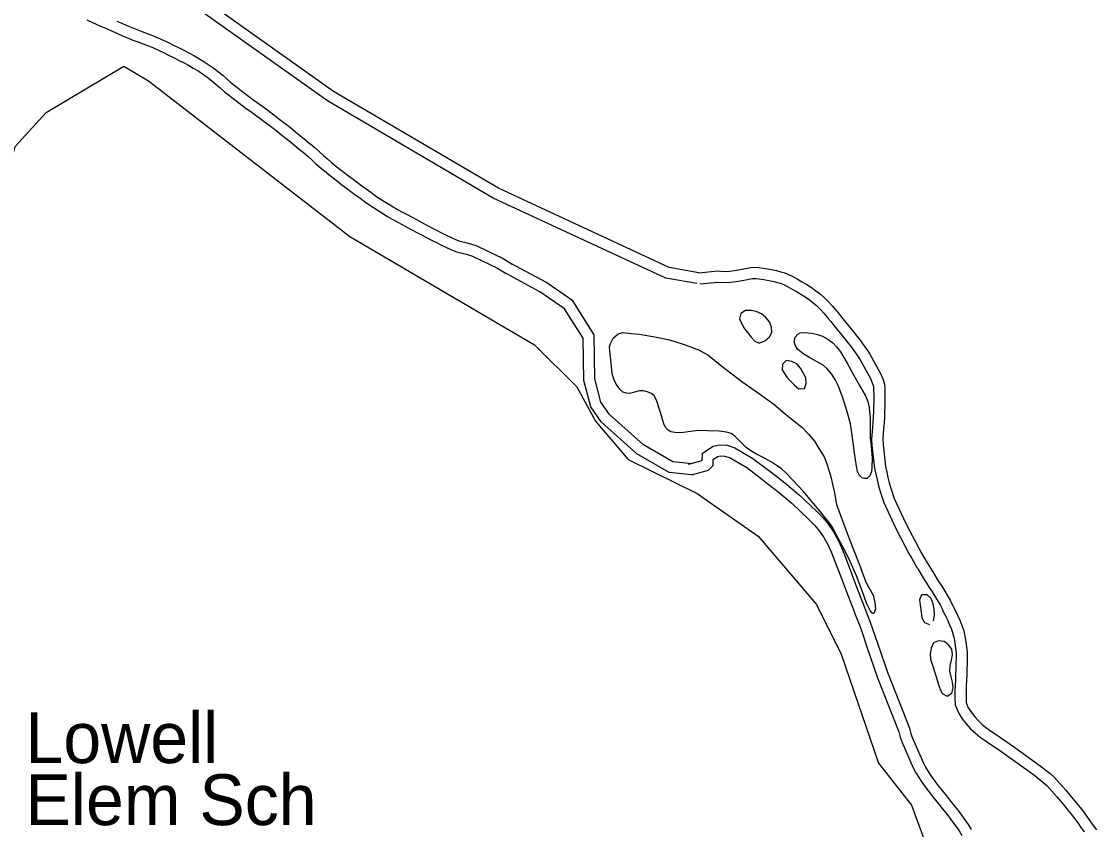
# Model space of a CAD drawing. Extents: x 1364363 to 1407445, y 538563 to 573342.
# Drawn here: x 1376165 to 1379335, y 562586 to 564968 of the extents above; entities that cross this region are included whole.
import ezdxf

# ---------------------------------------------------------------- set-up
doc = ezdxf.new("R2010")
doc.units = 0
for name, color, linetype in [('Exist Boundary Political City Limit New', 7, 'Continuous'), ('Exist Cultural Educational Facility High Label', 7, 'Continuous'), ('Exist Hydrographic Buffer Line', 7, 'Continuous'), ('Exist Hydrographic Creek Double Shore', 7, 'Continuous'), ('Exist Hydrographic Island Shore', 7, 'Continuous')]:
    doc.layers.add(name, color=color, linetype=linetype)

msp = doc.modelspace()

# ---------------------------------------------------------------- linework, layer by layer
at = {"layer": 'Exist Boundary Political City Limit New'}
for points in [[(1375206.1, 561788.9), (1375573.2, 562500.8), (1375743.9, 562885.2), (1375884.1, 563257.4), (1375926.8, 563806.6), (1376146.1, 564599.8), (1376237.6, 564700.5), (1376466.9, 564836.6)], [(1376466.9, 564836.6), (1376539.4, 564793.1), (1377132.8, 564334.4), (1377677.9, 564014.8), (1377802.1, 563890.9), (1377857.2, 563790.4), (1377953.9, 563676.6), (1378157.5, 563576.2), (1378336.9, 563450.7), (1378509.4, 563249.8), (1378581.9, 563102.5), (1378692.2, 562781.1), (1378788.9, 562657.2), (1378864.8, 562451.4)]]:
    msp.add_lwpolyline(points, dxfattribs=at)
at = {"layer": 'Exist Hydrographic Buffer Line'}
for points in [[(1378155.9, 564195.4), (1378064.8, 564211.6), (1377555.5, 564447.5), (1377066.8, 564734.5), (1376428.4, 565188.7)], [(1376445.6, 564969.7), (1376460.5, 564963.1), (1376475.4, 564956.6), (1376490.1, 564950.2), (1376504.5, 564944.4), (1376519.3, 564938.9), (1376534.8, 564933.3), (1376550.9, 564927.2), (1376567.1, 564920.5), (1376582.7, 564913.3), (1376597.8, 564906), (1376612.8, 564898.9), (1376627.9, 564891.5), (1376642.9, 564883.9), (1376658, 564876), (1376673, 564867.9), (1376687.8, 564859.4), (1376702.7, 564850.4), (1376717.3, 564840.8), (1376731.8, 564830.6), (1376745.6, 564819.9), (1376759, 564808.8), (1376771.9, 564797.6), (1376783.4, 564787.3), (1376846.8, 564738.7), (1376859.8, 564729.6), (1376873.5, 564719.8), (1376887, 564709.8), (1376900.4, 564699.8), (1376913.6, 564689.7), (1376926.7, 564679.6), (1376939.7, 564669.4), (1376952.7, 564659.3), (1376965.7, 564649), (1376978.7, 564638.6), (1377004.5, 564617.7), (1377017.2, 564607)], [(1377017.8, 564606.6), (1377030.4, 564595.6), (1377054.9, 564573.6), (1377066.8, 564563), (1377078.7, 564552.8), (1377090.9, 564543), (1377103.6, 564533.1), (1377116.5, 564523.2), (1377129.4, 564513.3), (1377142.3, 564503.5), (1377155.3, 564493.8), (1377168.4, 564484.1), (1377181.5, 564474.5), (1377194.6, 564465.1), (1377207.8, 564455.7), (1377220.4, 564446.9), (1377260.4, 564421.9), (1377273.8, 564414.4), (1377288.1, 564406.6), (1377302.4, 564398.8), (1377331.1, 564383.3), (1377345.6, 564375.7), (1377360, 564368), (1377374.4, 564360.4), (1377388.9, 564352.9), (1377403.4, 564345.4), (1377417.4, 564338.3), (1377444.9, 564325.4), (1377457.1, 564321.1), (1377471.5, 564317.6), (1377489.1, 564313.2), (1377507.7, 564306.6), (1377584.6, 564269.5), (1377611.5, 564253)], [(1378143.7, 563664.2), (1378084.9, 563670.3), (1377999.1, 563720.4), (1377898.5, 563809.6), (1377873.5, 563846.2), (1377855.5, 563914.3), (1377853.2, 564044.6), (1377790.1, 564144.5), (1377710.4, 564199.4), (1377610, 564253.8)], [(1378164.6, 564195), (1378218.4, 564199.9), (1378234.6, 564198.4), (1378254.3, 564199.6), (1378272.5, 564201.6), (1378290.1, 564204.7), (1378306, 564207.9), (1378319.8, 564210.2), (1378331, 564210.7), (1378354.1, 564207.4)], [(1378353.3, 564207.6), (1378368.9, 564205), (1378383.6, 564201.9), (1378397.7, 564198.2), (1378405, 564195.8)], [(1378405.1, 564195.8), (1378410, 564194.2), (1378421.8, 564188.2), (1378435.6, 564180.6), (1378449.6, 564172.7), (1378463, 564164.8), (1378475.8, 564156.5), (1378487.9, 564148), (1378499.2, 564139.1), (1378509.9, 564129.5), (1378520.5, 564119), (1378530.8, 564107.9), (1378540.9, 564096.3), (1378543.5, 564093.1)], [(1378543.7, 564092.9), (1378551.2, 564084), (1378561.3, 564071.4), (1378592.3, 564032.9), (1378602.5, 564020.2), (1378612.2, 564007.9), (1378621.5, 563995.3), (1378630.4, 563982.7), (1378638.2, 563970.6), (1378668, 563915.5), (1378673.5, 563903.2), (1378676.7, 563893.2), (1378677.4, 563881.7), (1378677.7, 563866.3), (1378677.7, 563850.5), (1378677.4, 563834.4), (1378677.1, 563818.3), (1378676.5, 563802.5), (1378675.6, 563786.9), (1378674.2, 563770.9), (1378671.5, 563737.3), (1378672.6, 563718.1), (1378680.4, 563651.1), (1378683.8, 563633.4), (1378687.5, 563616.6), (1378691.7, 563599.3), (1378696.9, 563582.3), (1378707.9, 563549.8), (1378743.1, 563473.5), (1378781.6, 563399.6), (1378790, 563384.7), (1378807.3, 563355.2)], [(1378131.7, 563663.2), (1378171.7, 563674.1), (1378172.5, 563695.1), (1378204.2, 563716.6), (1378224.2, 563720.5), (1378245.4, 563719.1), (1378267.9, 563711.7), (1378321.3, 563680.2), (1378367.2, 563645.7), (1378386.8, 563630.5), (1378415.9, 563607.9), (1378459.3, 563572), (1378509, 563524.2), (1378528.2, 563504.7), (1378544.4, 563485.3), (1378558.9, 563464), (1378573, 563438.9), (1378582.7, 563417.7), (1378593.3, 563390.8), (1378612, 563340.3), (1378627.3, 563301.3), (1378650.4, 563240.5), (1378653.7, 563232.3)], [(1378807.6, 563354.8), (1378823.8, 563328.2), (1378841.5, 563299.6), (1378850.5, 563286.3), (1378874.2, 563246), (1378880.2, 563234.5)], [(1378653.7, 563232.2), (1378667.4, 563197.4), (1378674.3, 563177.2)], [(1378880, 563234.8), (1378888.4, 563218), (1378895.3, 563203.8), (1378901.7, 563189.7), (1378907.3, 563176.2), (1378911.5, 563163.3), (1378914.7, 563149.7), (1378917.1, 563135), (1378920.8, 563105.9), (1378920.7, 563092.1), (1378920.3, 563076.1), (1378919.8, 563059.9), (1378919.2, 563043.6), (1378918.5, 563027.1), (1378918, 563010.5), (1378917.4, 562993.8), (1378917.2, 562976.2), (1378918.1, 562953.4), (1378927.4, 562929.9), (1378938.9, 562912.3), (1378950.3, 562897.3), (1378963.2, 562882.7), (1378977.6, 562869.8), (1378991.9, 562858.6), (1379006.3, 562848.2), (1379020.2, 562838.9), (1379045.5, 562821.6)], [(1378674.3, 563177.3), (1378688.7, 563135.6), (1378720.4, 563043.6)], [(1378720, 563044.9), (1378782.8, 562884.6), (1378787.5, 562868.1), (1378792.1, 562854.8), (1378824.1, 562782), (1378830.7, 562769.3), (1378838.3, 562756.7), (1378846.6, 562744.2), (1378855.7, 562731.7), (1378865.2, 562719), (1378874.9, 562706.4), (1378895.2, 562681.1), (1378905.6, 562668.3), (1378916, 562655.2), (1378926.4, 562642.1), (1378936.7, 562628.5), (1378946.8, 562614.6), (1378956.7, 562600.3), (1378965.6, 562586.4)], [(1379045.4, 562821.6), (1379073.7, 562802.1), (1379152.5, 562744.9), (1379164.6, 562735.4), (1379176.6, 562725.6), (1379187.9, 562715.7), (1379219.2, 562680.8)], [(1379219.2, 562680.8), (1379240.1, 562655.5), (1379250.4, 562643.1), (1379260.3, 562630.7), (1379270, 562618.2), (1379279.4, 562605.4), (1379288.9, 562592.2), (1379298.4, 562578.9)]]:
    msp.add_lwpolyline(points, dxfattribs=at)
at = {"layer": 'Exist Hydrographic Creek Double Shore'}
for points in [[(1378161.6, 564227.7), (1378074.8, 564243.2), (1377570.8, 564476.6), (1377084.7, 564762), (1376443.7, 565218.1)], [(1376357.4, 564973.4), (1376372.3, 564966.6), (1376387.3, 564959.9), (1376402.3, 564953.1), (1376417.2, 564946.4), (1376432.3, 564939.7), (1376447.3, 564933.1), (1376462.3, 564926.5), (1376477.4, 564920), (1376492.6, 564913.8), (1376508, 564908.1), (1376523.5, 564902.5), (1376538.8, 564896.7), (1376553.9, 564890.4), (1376568.8, 564883.6), (1376583.6, 564876.5), (1376598.5, 564869.3), (1376613.3, 564862.1), (1376627.9, 564854.7), (1376642.6, 564847.1), (1376656.9, 564839.2), (1376671.2, 564831.1), (1376685.2, 564822.6), (1376698.9, 564813.7), (1376712.2, 564804.2), (1376725.1, 564794.2), (1376737.8, 564783.7), (1376750.2, 564773), (1376762.5, 564762), (1376827.4, 564712.2), (1376840.9, 564702.8), (1376854.2, 564693.2), (1376867.4, 564683.5), (1376880.6, 564673.7), (1376893.6, 564663.7), (1376906.6, 564653.7), (1376919.5, 564643.6), (1376932.4, 564633.5), (1376945.3, 564623.3), (1376958.2, 564613.1), (1376970.9, 564602.7), (1376983.6, 564592.4), (1376996.2, 564581.8)], [(1376996.2, 564581.8), (1377008.6, 564571), (1377020.8, 564560.1), (1377033, 564549.1), (1377045.3, 564538.2), (1377057.8, 564527.6), (1377070.5, 564517.3), (1377083.4, 564507.2), (1377096.5, 564497.2), (1377109.5, 564487.2), (1377122.6, 564477.3), (1377135.7, 564467.4), (1377149, 564457.7), (1377162.2, 564448), (1377175.5, 564438.4), (1377188.8, 564428.9), (1377202.3, 564419.5), (1377243.7, 564393.7), (1377257.9, 564385.7), (1377272.4, 564377.8), (1377286.8, 564370), (1377301.2, 564362.2), (1377315.7, 564354.4), (1377330.2, 564346.7), (1377344.7, 564339), (1377359.2, 564331.4), (1377373.8, 564323.8), (1377388.4, 564316.3), (1377403, 564308.8), (1377432.3, 564295.1), (1377447.6, 564289.6), (1377463.7, 564285.7), (1377479.7, 564281.8), (1377495.1, 564276.3), (1377568.8, 564240.7), (1377594.3, 564225)], [(1378161.6, 564227.7), (1378218.4, 564232.8), (1378235.1, 564231.3), (1378251.5, 564232.3), (1378267.8, 564234.1), (1378284, 564236.9), (1378300.1, 564240.2), (1378316.3, 564242.8), (1378332.5, 564243.7), (1378358.8, 564239.9)], [(1378358.8, 564239.9), (1378375, 564237.2), (1378391.1, 564233.9), (1378407.1, 564229.7), (1378415.4, 564227)], [(1378140.4, 563631.6), (1378074.4, 563638.4), (1377979.7, 563693.7), (1377873.7, 563787.7), (1377843.3, 563832.4), (1377822.8, 563909.8), (1377820.5, 564034.9), (1377766, 564121.3), (1377693.2, 564171.4), (1377594.3, 564225)], [(1378415.4, 564227), (1378422.6, 564224.5), (1378437.2, 564217.2), (1378451.6, 564209.2), (1378466, 564201.1), (1378480.3, 564192.7), (1378494.1, 564183.7), (1378507.5, 564174.3), (1378520.4, 564164.2), (1378532.5, 564153.3), (1378544, 564141.9), (1378555.2, 564129.9), (1378566, 564117.5), (1378568.8, 564114)], [(1378568.8, 564114), (1378576.5, 564104.8), (1378586.9, 564091.9), (1378617.9, 564053.5), (1378628.2, 564040.7), (1378638.4, 564027.7), (1378648.1, 564014.5), (1378657.5, 564001.1), (1378666.5, 563987.3), (1378697.4, 563930), (1378704.2, 563915), (1378709.2, 563899.4), (1378710.2, 563883), (1378710.5, 563866.6), (1378710.5, 563850.2), (1378710.2, 563833.8), (1378709.9, 563817.4), (1378709.3, 563800.9), (1378708.3, 563784.4), (1378706.8, 563768.2), (1378704.4, 563737), (1378705.3, 563720.9), (1378712.8, 563656.2), (1378716, 563640), (1378719.5, 563624), (1378723.4, 563608), (1378728.2, 563592.4), (1378738.4, 563562), (1378772.6, 563488), (1378810.5, 563415.3), (1378818.5, 563401), (1378835.6, 563371.8)], [(1378140.4, 563631.6), (1378190.4, 563645.2), (1378204, 563658.9), (1378204.7, 563677.3), (1378217.1, 563685.7), (1378226.3, 563687.5), (1378239.1, 563686.6), (1378254.3, 563681.7), (1378303.1, 563652.9), (1378347.3, 563619.7), (1378366.7, 563604.6), (1378395.4, 563582.3), (1378437.4, 563547.5), (1378485.9, 563500.9), (1378503.8, 563482.6), (1378518.2, 563465.4), (1378531, 563446.7), (1378543.7, 563424), (1378552.5, 563404.8), (1378562.6, 563379.1), (1378581.4, 563328.6), (1378596.7, 563289.5), (1378619.8, 563228.7), (1378623.2, 563220.1)], [(1378835.6, 563371.8), (1378851.7, 563345.3), (1378869, 563317.4), (1378878.3, 563303.9), (1378903, 563261.9), (1378909.3, 563249.5)], [(1378909.3, 563249.5), (1378917.8, 563232.6), (1378925, 563217.7), (1378931.8, 563202.7), (1378938, 563187.6), (1378943.2, 563172.1), (1378946.9, 563156), (1378949.5, 563139.8), (1378953.6, 563107.9), (1378953.5, 563091.6), (1378953.1, 563075.2), (1378952.6, 563058.8), (1378952, 563042.3), (1378951.3, 563025.9), (1378950.8, 563009.5), (1378950.2, 562993.1), (1378950, 562976.6), (1378950.7, 562960.2), (1378956.7, 562945.1), (1378965.7, 562931.2), (1378975.7, 562918.2), (1378986.5, 562905.9), (1378998.7, 562894.9), (1379011.7, 562884.8), (1379025, 562875.1), (1379038.6, 562866.1), (1379064, 562848.6)], [(1378623.2, 563220.1), (1378636.6, 563186.1), (1378643.3, 563166.6)], [(1378643.3, 563166.6), (1378657.7, 563124.9), (1378689.4, 563032.9)], [(1378689.4, 563032.9), (1378751.7, 562874.1), (1378756.2, 562858.2), (1378761.5, 562842.8), (1378794.5, 562767.8), (1378802.1, 562753.3), (1378810.5, 562739.2), (1378819.6, 562725.5), (1378829.3, 562712.2), (1378839.1, 562699.1), (1378849.2, 562686.1), (1378859.4, 562673.3), (1378869.7, 562660.5), (1378880, 562647.7), (1378890.3, 562634.9), (1378900.4, 562622), (1378910.4, 562608.9), (1378920, 562595.7), (1378929.3, 562582.1), (1378937.9, 562568.7)], [(1379064, 562848.6), (1379092.7, 562828.9), (1379172.2, 562771.1), (1379185.1, 562761), (1379197.8, 562750.6), (1379210.1, 562739.8), (1379244.5, 562701.7)], [(1379244.5, 562701.7), (1379265.4, 562676.4), (1379275.9, 562663.8), (1379286.1, 562651), (1379296.2, 562638), (1379305.9, 562624.7), (1379315.5, 562611.4), (1379325.1, 562598.1), (1379334.7, 562584.7)]]:
    msp.add_lwpolyline(points, dxfattribs=at)
at = {"layer": 'Exist Hydrographic Island Shore'}
for points in [[(1378330.7, 564113.4), (1378316.2, 564116.7), (1378299.8, 564116.4), (1378285.8, 564107.6), (1378282, 564091.5), (1378295.2, 564065), (1378315.9, 564037.6), (1378326.9, 564025.8), (1378340.1, 564020.4), (1378356.9, 564026.5), (1378370.8, 564038.5)], [(1378370.8, 564038.5), (1378377.7, 564051.4), (1378376, 564067.5), (1378370.6, 564083.1), (1378360, 564095.7), (1378347.2, 564106.1), (1378330.7, 564113.4)], [(1378660.2, 563245.7), (1378656.6, 563253.4), (1378643.8, 563289.9), (1378626.5, 563333.5), (1378608.5, 563376), (1378592.1, 563408.5), (1378567.7, 563454.1), (1378555.2, 563478.7), (1378546.6, 563491.4), (1378516.1, 563528.9), (1378470, 563583.9), (1378441.1, 563613.7), (1378417.9, 563638.6), (1378406.3, 563648.9), (1378393.5, 563658.7), (1378378.4, 563668.5), (1378357.8, 563679.7), (1378329.8, 563693.5), (1378315.1, 563702.7), (1378301.2, 563712.5), (1378298.4, 563715.3), (1378285.5, 563728.3), (1378268.1, 563745.9), (1378257.1, 563753.3), (1378244.1, 563757.8), (1378221.7, 563760.7), (1378187.3, 563761.5), (1378161.8, 563762.2), (1378137.5, 563759.8), (1378110.1, 563755.7), (1378091.2, 563756.2), (1378079.9, 563758.3), (1378071.2, 563763.8), (1378064.2, 563771.1), (1378059.2, 563782.5), (1378048.7, 563815.3), (1378037.1, 563851.8), (1378030.3, 563864.4), (1378022.2, 563871.6), (1378009.9, 563876.7), (1377997.5, 563879.4), (1377987.3, 563879), (1377972.5, 563875.3), (1377957.6, 563871.5), (1377948.7, 563872.3), (1377938.1, 563875.5), (1377928.8, 563884.1), (1377917.9, 563899.1), (1377911.1, 563913.5), (1377906.7, 563930.2), (1377902.4, 563970.6), (1377899.5, 563997.3), (1377899.1, 564009.2), (1377901.8, 564019.2), (1377909.8, 564035), (1377924.4, 564047.6), (1377938.4, 564051.3), (1377962.4, 564048.7), (1377986.3, 564046.1), (1378032.2, 564039), (1378076, 564029.9), (1378109.7, 564019.1), (1378135.6, 564010.5), (1378161.3, 563999.9), (1378188.9, 563985.2), (1378230.1, 563952.2), (1378289.1, 563906.7), (1378348, 563865.3), (1378383.5, 563840.4), (1378416.8, 563811.6), (1378442.2, 563791), (1378465.8, 563772.4), (1378485.3, 563751.9), (1378502.8, 563731.4), (1378516.3, 563709.1), (1378531.7, 563684.7), (1378539.2, 563664.5), (1378550.4, 563630.2), (1378561.3, 563584), (1378568.2, 563543.8), (1378592.6, 563477.1), (1378615.3, 563418.6), (1378636, 563366), (1378654.8, 563315.5), (1378675.8, 563277), (1378680.2, 563259.4)], [(1378542.9, 564031.7), (1378557.3, 564021.2), (1378568.4, 564009.5), (1378580.1, 563994), (1378599.1, 563961.1), (1378618.6, 563926.3), (1378636.2, 563894.8), (1378653.3, 563864.5), (1378660.5, 563847.8), (1378664.6, 563830.5), (1378667, 563797.4), (1378666.9, 563740.3), (1378670.1, 563716.7), (1378673.1, 563682.3), (1378672.4, 563653.7), (1378670.9, 563641), (1378666.1, 563628.5), (1378658.4, 563621), (1378650.7, 563620.6), (1378644.4, 563622), (1378636.3, 563629.8), (1378630.2, 563641.4), (1378626.8, 563656.8), (1378621.3, 563696.3), (1378614.4, 563748.5), (1378609.3, 563781.7), (1378600.6, 563814.3), (1378587.1, 563858.5), (1378573.4, 563895), (1378564.2, 563912.4), (1378553.2, 563929.8), (1378540.9, 563944.1), (1378528.3, 563954.6), (1378511.4, 563964.5), (1378488.9, 563976.5), (1378468.8, 563989.1), (1378453.8, 564000.9), (1378448.3, 564009.9), (1378444.1, 564020.2), (1378443.7, 564028.5), (1378445.8, 564037.3), (1378454.2, 564046), (1378461.3, 564050.2), (1378471.5, 564051.3), (1378495.6, 564049.4), (1378512, 564045.2), (1378527.2, 564040.4), (1378542.9, 564031.7)], [(1378421.1, 563919.3), (1378432.5, 563907.4), (1378444, 563895.7), (1378457.1, 563885.5), (1378473.8, 563886), (1378478.6, 563900.5), (1378477.3, 563917.3), (1378470.2, 563932.3), (1378461.4, 563946.3), (1378450.9, 563958.7), (1378436.2, 563966.1), (1378420, 563969), (1378408.6, 563957.8), (1378407.9, 563941.5), (1378421.1, 563919.3)], [(1378680.2, 563259.4), (1378681.3, 563254.9), (1378682.9, 563236.8), (1378678.6, 563224.9), (1378675.3, 563222.4), (1378671.9, 563224.6), (1378666.8, 563231.8), (1378660.2, 563245.7)], [(1378854.4, 563201.3), (1378857, 563218.8), (1378855.9, 563235.2), (1378852.8, 563251.5), (1378847, 563266.6), (1378835, 563277.8), (1378818.8, 563277.4), (1378813.2, 563262.7), (1378817.7, 563226.7), (1378820, 563210.2), (1378827.5, 563196.2), (1378842.4, 563190.8)], [(1378853, 563064.4), (1378862.8, 563032.7), (1378867.7, 563016.8), (1378873.2, 563001.5), (1378880, 562987), (1378894.5, 562978.8), (1378907.8, 562988.4), (1378911.8, 563004.1), (1378910.5, 563020.5), (1378906.2, 563036.5), (1378902.6, 563052.5), (1378903.3, 563068.6), (1378907, 563084.8), (1378909.7, 563101.1), (1378908, 563117.2), (1378898.4, 563130.6), (1378885.2, 563140.3), (1378868.8, 563142.3), (1378854.4, 563136), (1378847.5, 563121), (1378844.5, 563104.9), (1378845.4, 563088.5), (1378853, 563064.4)]]:
    msp.add_lwpolyline(points, dxfattribs=at)

# ---------------------------------------------------------------- texts
at = {"layer": 'Exist Cultural Educational Facility High Label'}
for s, p in [('Lowell ', (1376176.5, 562781.6)), ('Elem Sch', (1376176.5, 562598.8))]:
    msp.add_text(s, height=150, dxfattribs=at).set_placement(p)

doc.saveas('drawing.dxf')
